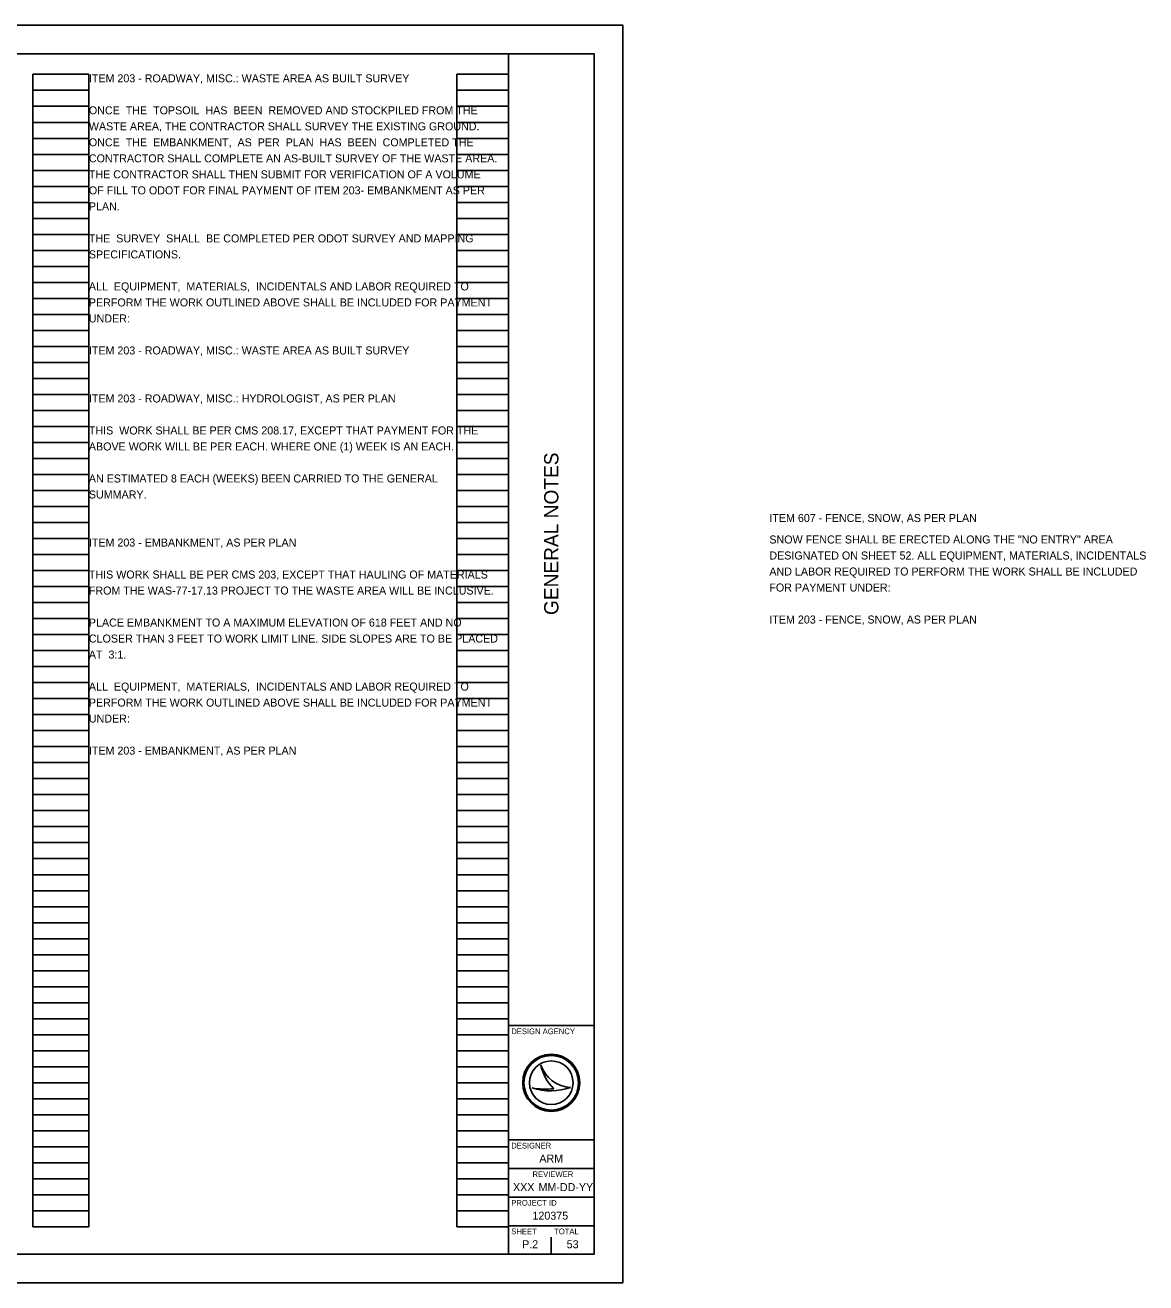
# Model space of a CAD drawing. Extents: x 0 to 43.2, y 0 to 22.
# Drawn here: x 23.55 to 43.15, y 0 to 22 of the extents above; entities that cross this region are included whole.
import ezdxf

# ---------------------------------------------------------------- set-up
doc = ezdxf.new("R2010")
doc.units = 0
for name, color, linetype in [('SH_Border', 7, 'Continuous'), ('SH_Cut_Line', 7, 'Continuous'), ('SH_Data', 7, 'Continuous'), ('SH_Text', 7, 'Continuous')]:
    doc.layers.add(name, color=color, linetype=linetype)

msp = doc.modelspace()

# ---------------------------------------------------------------- linework, layer by layer
at = {"layer": 'SH_Border'}
for p, q in [((32, 0.5), (32, 21.5)), ((32, 4.5), (33.5, 4.5)), ((32, 2.5), (33.5, 2.5)), ((32, 2), (33.5, 2)), ((32, 1.5), (33.5, 1.5)), ((32, 1), (33.5, 1))]:
    msp.add_line(p, q, dxfattribs=at)
msp.add_lwpolyline([(1.5, 21.5), (33.5, 21.5), (33.5, 0.5), (1.5, 0.5)], close=True, dxfattribs=at)
at = {"layer": 'SH_Cut_Line'}
msp.add_lwpolyline([(0, 0), (34, 0), (34, 22), (0, 22)], close=True, dxfattribs=at)
at = {"layer": 'SH_Data'}
for p, q in [((23.68, 0.98), (23.68, 21.14)), ((23.68, 21.14), (24.66, 21.14)), ((24.66, 0.98), (24.66, 21.14)), ((31.1, 0.98), (31.1, 21.14)), ((31.1, 21.14), (32, 21.14)), ((32, 0.98), (32, 21.14)), ((23.68, 20.86), (24.66, 20.86)), ((31.1, 20.86), (32, 20.86)), ((23.68, 20.58), (24.66, 20.58)), ((31.1, 20.58), (32, 20.58)), ((23.68, 20.3), (24.66, 20.3)), ((31.1, 20.3), (32, 20.3)), ((23.68, 20.02), (24.66, 20.02)), ((31.1, 20.02), (32, 20.02)), ((23.68, 19.74), (24.66, 19.74)), ((31.1, 19.74), (32, 19.74)), ((23.68, 19.46), (24.66, 19.46)), ((31.1, 19.46), (32, 19.46)), ((23.68, 19.18), (24.66, 19.18)), ((31.1, 19.18), (32, 19.18)), ((23.68, 18.9), (24.66, 18.9)), ((31.1, 18.9), (32, 18.9)), ((23.68, 18.62), (24.66, 18.62)), ((31.1, 18.62), (32, 18.62)), ((23.68, 18.34), (24.66, 18.34)), ((31.1, 18.34), (32, 18.34)), ((23.68, 18.06), (24.66, 18.06)), ((31.1, 18.06), (32, 18.06)), ((23.68, 17.78), (24.66, 17.78)), ((31.1, 17.78), (32, 17.78)), ((23.68, 17.5), (24.66, 17.5)), ((31.1, 17.5), (32, 17.5)), ((23.68, 17.22), (24.66, 17.22)), ((31.1, 17.22), (32, 17.22)), ((23.68, 16.94), (24.66, 16.94)), ((31.1, 16.94), (32, 16.94)), ((23.68, 16.66), (24.66, 16.66)), ((31.1, 16.66), (32, 16.66)), ((23.68, 16.38), (24.66, 16.38)), ((31.1, 16.38), (32, 16.38)), ((23.68, 16.1), (24.66, 16.1)), ((31.1, 16.1), (32, 16.1)), ((23.68, 15.82), (24.66, 15.82)), ((31.1, 15.82), (32, 15.82)), ((23.68, 15.54), (24.66, 15.54)), ((31.1, 15.54), (32, 15.54)), ((23.68, 15.26), (24.66, 15.26)), ((31.1, 15.26), (32, 15.26)), ((23.68, 14.98), (24.66, 14.98)), ((31.1, 14.98), (32, 14.98)), ((23.68, 14.7), (24.66, 14.7)), ((31.1, 14.7), (32, 14.7)), ((23.68, 14.42), (24.66, 14.42)), ((31.1, 14.42), (32, 14.42)), ((23.68, 14.14), (24.66, 14.14)), ((31.1, 14.14), (32, 14.14)), ((23.68, 13.86), (24.66, 13.86)), ((31.1, 13.86), (32, 13.86)), ((23.68, 13.58), (24.66, 13.58)), ((31.1, 13.58), (32, 13.58)), ((23.68, 13.3), (24.66, 13.3)), ((31.1, 13.3), (32, 13.3)), ((23.68, 13.02), (24.66, 13.02)), ((31.1, 13.02), (32, 13.02)), ((23.68, 12.74), (24.66, 12.74)), ((31.1, 12.74), (32, 12.74)), ((23.68, 12.46), (24.66, 12.46)), ((31.1, 12.46), (32, 12.46)), ((23.68, 12.18), (24.66, 12.18)), ((31.1, 12.18), (32, 12.18)), ((23.68, 11.9), (24.66, 11.9)), ((31.1, 11.9), (32, 11.9)), ((23.68, 11.62), (24.66, 11.62)), ((31.1, 11.62), (32, 11.62)), ((23.68, 11.34), (24.66, 11.34)), ((31.1, 11.34), (32, 11.34)), ((23.68, 11.06), (24.66, 11.06)), ((31.1, 11.06), (32, 11.06)), ((23.68, 10.78), (24.66, 10.78)), ((31.1, 10.78), (32, 10.78)), ((23.68, 10.5), (24.66, 10.5)), ((31.1, 10.5), (32, 10.5)), ((23.68, 10.22), (24.66, 10.22)), ((31.1, 10.22), (32, 10.22)), ((23.68, 9.94), (24.66, 9.94)), ((31.1, 9.94), (32, 9.94)), ((23.68, 9.66), (24.66, 9.66)), ((31.1, 9.66), (32, 9.66)), ((23.68, 9.38), (24.66, 9.38)), ((31.1, 9.38), (32, 9.38)), ((23.68, 9.1), (24.66, 9.1)), ((31.1, 9.1), (32, 9.1)), ((23.68, 8.82), (24.66, 8.82)), ((31.1, 8.82), (32, 8.82)), ((23.68, 8.54), (24.66, 8.54)), ((31.1, 8.54), (32, 8.54)), ((23.68, 8.26), (24.66, 8.26)), ((31.1, 8.26), (32, 8.26)), ((23.68, 7.98), (24.66, 7.98)), ((31.1, 7.98), (32, 7.98)), ((23.68, 7.7), (24.66, 7.7)), ((31.1, 7.7), (32, 7.7)), ((23.68, 7.42), (24.66, 7.42)), ((31.1, 7.42), (32, 7.42)), ((23.68, 7.14), (24.66, 7.14)), ((31.1, 7.14), (32, 7.14)), ((23.68, 6.86), (24.66, 6.86)), ((31.1, 6.86), (32, 6.86)), ((23.68, 6.58), (24.66, 6.58)), ((31.1, 6.58), (32, 6.58)), ((23.68, 6.3), (24.66, 6.3)), ((31.1, 6.3), (32, 6.3)), ((23.68, 6.02), (24.66, 6.02)), ((31.1, 6.02), (32, 6.02)), ((23.68, 5.74), (24.66, 5.74)), ((31.1, 5.74), (32, 5.74)), ((23.68, 5.46), (24.66, 5.46)), ((31.1, 5.46), (32, 5.46)), ((23.68, 5.18), (24.66, 5.18)), ((31.1, 5.18), (32, 5.18)), ((23.68, 4.9), (24.66, 4.9)), ((31.1, 4.9), (32, 4.9)), ((23.68, 4.62), (24.66, 4.62)), ((31.1, 4.62), (32, 4.62)), ((23.68, 4.34), (24.66, 4.34)), ((31.1, 4.34), (32, 4.34)), ((23.68, 4.06), (24.66, 4.06)), ((31.1, 4.06), (32, 4.06)), ((23.68, 3.78), (24.66, 3.78)), ((31.1, 3.78), (32, 3.78)), ((32.567, 3.81), (32.567, 3.81)), ((23.68, 3.5), (24.66, 3.5)), ((31.1, 3.5), (32, 3.5)), ((32.417, 3.41), (32.417, 3.41)), ((32.75, 3.5), (32.75, 3.5)), ((33.087, 3.419), (33.087, 3.419)), ((23.68, 3.22), (24.66, 3.22)), ((31.1, 3.22), (32, 3.22)), ((23.68, 2.94), (24.66, 2.94)), ((31.1, 2.94), (32, 2.94)), ((23.68, 2.66), (24.66, 2.66)), ((31.1, 2.66), (32, 2.66)), ((23.68, 2.38), (24.66, 2.38)), ((31.1, 2.38), (32, 2.38)), ((23.68, 2.1), (24.66, 2.1)), ((31.1, 2.1), (32, 2.1)), ((23.68, 1.82), (24.66, 1.82)), ((31.1, 1.82), (32, 1.82)), ((23.68, 1.54), (24.66, 1.54)), ((31.1, 1.54), (32, 1.54)), ((23.68, 1.26), (24.66, 1.26)), ((31.1, 1.26), (32, 1.26)), ((23.68, 0.98), (24.66, 0.98)), ((31.1, 0.98), (32, 0.98)), ((32.375, 0.675), (32.375, 0.675)), ((32.75, 0.5), (32.75, 0.8))]:
    msp.add_line(p, q, dxfattribs=at)
for radius in [0.5, 0.477, 0.477, 0.382]:
    msp.add_circle((32.75, 3.5), radius, dxfattribs=at)
for centre, radius, start, end in [((33.116, 3.998), 0.58, 198.9257, 198.9319), ((33.347, 3.97), 0.796, 191.6379, 191.6421), ((33.116, 3.998), 0.58, 198.9319, 267.1657), ((33.347, 3.97), 0.796, 191.6421, 226.0947), ((32.739, 4.37), 1.013, 251.4576, 290.0832), ((32.648, 4.654), 1.266, 259.4964, 259.4995), ((32.739, 4.37), 1.013, 251.4527, 251.4576), ((32.648, 4.654), 1.266, 259.4995, 276.6672)]:
    msp.add_arc(centre, radius, start, end, dxfattribs=at)

# ---------------------------------------------------------------- texts
msp.add_text('GENERAL NOTES', height=0.25, rotation=90, dxfattribs=at).set_placement((32.875, 11.682))
for s, height, p in [('DESIGN AGENCY', 0.1, (32.05, 4.35)), ('DESIGNER', 0.1, (32.05, 2.35)), ('ARM', 0.14, (32.541, 2.105)), ('REVIEWER', 0.1, (32.422, 1.85)), ('XXX', 0.14, (32.081, 1.605)), ('MM-DD-YY', 0.14, (32.527, 1.605)), ('PROJECT ID', 0.1, (32.05, 1.35)), ('120375', 0.14, (32.421, 1.105)), ('SHEET', 0.1, (32.05, 0.85)), ('TOTAL', 0.1, (32.8, 0.85)), ('P.2', 0.14, (32.24, 0.605)), ('53', 0.14, (33.02, 0.605))]:
    msp.add_text(s, height=height, dxfattribs=at).set_placement(p)
at = {"layer": 'SH_Text'}
for s, p in [('ITEM 203 - ROADWAY, MISC.: WASTE AREA AS BUILT SURVEY', (24.66, 21)), ('ONCE  THE  TOPSOIL  HAS  BEEN  REMOVED AND STOCKPILED FROM THE', (24.66, 20.44)), ('WASTE AREA, THE CONTRACTOR SHALL SURVEY THE EXISTING GROUND.', (24.66, 20.16)), ('ONCE  THE  EMBANKMENT,  AS  PER  PLAN  HAS  BEEN  COMPLETED THE', (24.66, 19.88)), ('CONTRACTOR SHALL COMPLETE AN AS-BUILT SURVEY OF THE WASTE AREA.', (24.66, 19.6)), ('THE CONTRACTOR SHALL THEN SUBMIT FOR VERIFICATION OF A VOLUME', (24.66, 19.32)), ('OF FILL TO ODOT FOR FINAL PAYMENT OF ITEM 203- EMBANKMENT AS PER', (24.66, 19.04)), ('PLAN.', (24.66, 18.76)), ('THE  SURVEY  SHALL  BE COMPLETED PER ODOT SURVEY AND MAPPING', (24.66, 18.2)), ('SPECIFICATIONS.', (24.66, 17.92)), ('ALL  EQUIPMENT,  MATERIALS,  INCIDENTALS AND LABOR REQUIRED TO', (24.66, 17.36)), ('PERFORM THE WORK OUTLINED ABOVE SHALL BE INCLUDED FOR PAYMENT', (24.66, 17.08)), ('UNDER:', (24.66, 16.8)), ('ITEM 203 - ROADWAY, MISC.: WASTE AREA AS BUILT SURVEY', (24.66, 16.24)), ('ITEM 203 - ROADWAY, MISC.: HYDROLOGIST, AS PER PLAN', (24.66, 15.4)), ('THIS  WORK SHALL BE PER CMS 208.17, EXCEPT THAT PAYMENT FOR THE', (24.66, 14.84)), ('ABOVE WORK WILL BE PER EACH. WHERE ONE (1) WEEK IS AN EACH.', (24.66, 14.56)), ('AN ESTIMATED 8 EACH (WEEKS) BEEN CARRIED TO THE GENERAL', (24.66, 14)), ('SUMMARY.', (24.66, 13.72)), ('ITEM 607 - FENCE, SNOW, AS PER PLAN', (36.566, 13.309)), ('ITEM 203 - EMBANKMENT, AS PER PLAN', (24.66, 12.88)), ('SNOW FENCE SHALL BE ERECTED ALONG THE "NO ENTRY" AREA ', (36.566, 12.933)), ('DESIGNATED ON SHEET 52. ALL EQUIPMENT, MATERIALS, INCIDENTALS', (36.566, 12.653)), ('THIS WORK SHALL BE PER CMS 203, EXCEPT THAT HAULING OF MATERIALS', (24.66, 12.32)), ('AND LABOR REQUIRED TO PERFORM THE WORK SHALL BE INCLUDED ', (36.566, 12.373)), ('FROM THE WAS-77-17.13 PROJECT TO THE WASTE AREA WILL BE INCLUSIVE.', (24.66, 12.04)), ('FOR PAYMENT UNDER:', (36.566, 12.093)), ('ITEM 203 - FENCE, SNOW, AS PER PLAN', (36.566, 11.533)), ('PLACE EMBANKMENT TO A MAXIMUM ELEVATION OF 618 FEET AND NO', (24.66, 11.48)), ('CLOSER THAN 3 FEET TO WORK LIMIT LINE. SIDE SLOPES ARE TO BE PLACED', (24.66, 11.2)), ('AT  3:1.', (24.66, 10.92)), ('ALL  EQUIPMENT,  MATERIALS,  INCIDENTALS AND LABOR REQUIRED TO', (24.66, 10.36)), ('PERFORM THE WORK OUTLINED ABOVE SHALL BE INCLUDED FOR PAYMENT', (24.66, 10.08)), ('UNDER:', (24.66, 9.8)), ('ITEM 203 - EMBANKMENT, AS PER PLAN', (24.66, 9.24))]:
    msp.add_text(s, height=0.14, dxfattribs=at).set_placement(p)

doc.saveas('drawing.dxf')
